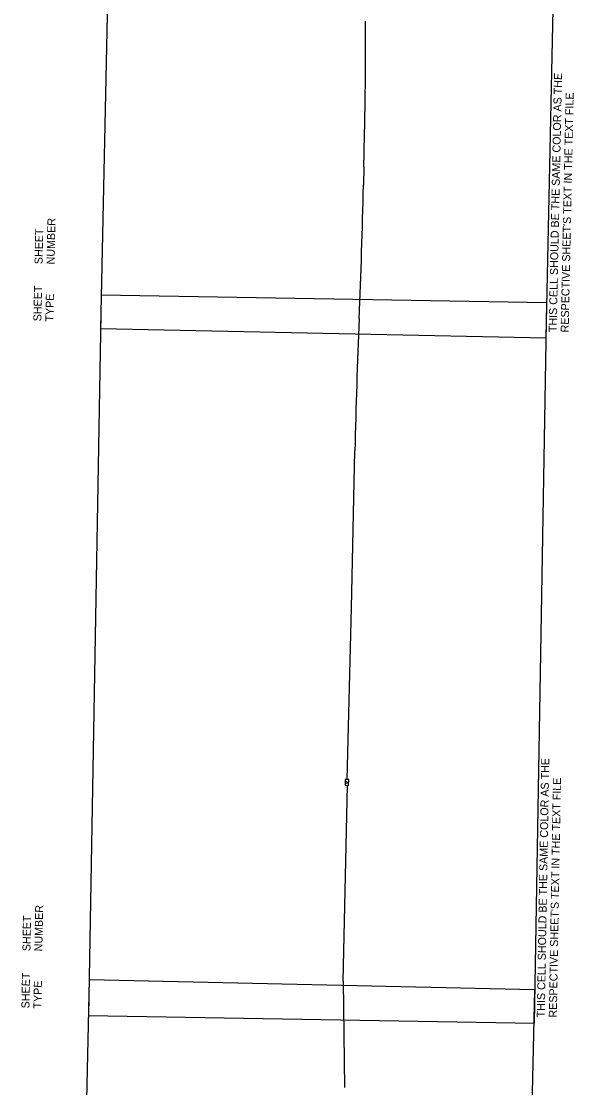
# Model space of a CAD drawing. Extents: x 601462 to 605493, y 331960 to 402715.
# Drawn here: x 603621 to 604829, y 342262 to 344593 of the extents above; entities that cross this region are included whole.
import ezdxf

# ---------------------------------------------------------------- set-up
doc = ezdxf.new("R2010")
doc.units = 0
for name, color, linetype in [('P_FTMS', 7, 'Continuous'), ('P_FTMSConduit', 7, 'Continuous'), ('P_MISC_TXT_2A (Construction)', 7, 'Continuous'), ('P_MISC_TXT_2B (Construction)', 7, 'Continuous')]:
    doc.layers.add(name, color=color, linetype=linetype)

# ---------------------------------------------------------------- blocks, each defined once
blk = doc.blocks.new('FTMS_FCV')
at = {"layer": 'P_FTMS'}
blk.add_line((13, 16), (1, -22), dxfattribs=at)
blk.add_lwpolyline([(39, 24), (-39, 24), (-39, -24), (39, -24)], close=True, dxfattribs=at)
blk.add_lwpolyline([(-12, 16), (1, -22)], dxfattribs=at)

msp = doc.modelspace()

# ---------------------------------------------------------------- linework, layer by layer
at = {"layer": 'P_FTMSConduit'}
for p, q in [((604369.9, 344275.3), (604369, 344235.3)), ((604342.8, 343310.7), (604350.3, 343653.9)), ((604333.3, 342935.7), (604342.8, 343310.7)), ((604325, 342494.7), (604334.3, 342922.8)), ((604325, 342495), (604327.2, 342262.1))]:
    msp.add_line(p, q, dxfattribs=at)
for centre, radius, start, end in [((590213.5, 344584.5), 14160.3, 359.37156, 0.03535), ((589440.8, 344649.6), 14933.7, 358.56399, 359.15428), ((590212.6, 344544.5), 14159.8, 357.56708, 358.74902), ((618387.2, 343347.4), 14040.2, 177.56708, 178.74902)]:
    msp.add_arc(centre, radius, start, end, dxfattribs=at)
at = {"layer": 'P_MISC_TXT_2A (Construction)'}
for points in [[(604768.7, 343901), (604801.9, 345475.6), (603827.1, 345496.2), (603793.9, 343921.5)], [(604708.5, 340900.9), (604744.2, 342475.5), (603769.4, 342497.6), (603733.8, 340923)]]:
    msp.add_lwpolyline(points, close=True, dxfattribs=at)
at = {"layer": 'P_MISC_TXT_2B (Construction)'}
msp.add_lwpolyline([(604742.8, 342403), (604770.2, 343977.8), (603795.4, 343994.8), (603767.9, 342420)], close=True, dxfattribs=at)

# ---------------------------------------------------------------- block references
at = {"layer": 'P_FTMS', "xscale": 0.1640416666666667, "yscale": 0.16404166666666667, "rotation": 87.23689791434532}
msp.add_blockref('FTMS_FCV', (604333, 342929.3), dxfattribs=at)

# ---------------------------------------------------------------- texts
at = {"layer": 'P_MISC_TXT_2A (Construction)'}
for s, p in [('THIS CELL SHOULD BE THE SAME COLOR AS THE', (604791.6, 343913.5)), ("RESPECTIVE SHEET'S TEXT IN THE TEXT FILE", (604817.8, 343912.9)), ('NUMBER', (603693.2, 344061.6)), ('SHEET', (603667, 344062.2)), ('SHEET', (603664.4, 343937.2)), ('TYPE', (603690.6, 343936.6))]:
    msp.add_text(s, height=17.5, rotation=88.794, dxfattribs=at).set_placement(p)
at = {"layer": 'P_MISC_TXT_2B (Construction)'}
for s, p in [('THIS CELL SHOULD BE THE SAME COLOR AS THE', (604765.6, 342415.6)), ("RESPECTIVE SHEET'S TEXT IN THE TEXT FILE", (604791.9, 342415.1)), ('NUMBER', (603666.7, 342559.8)), ('SHEET', (603640.5, 342560.2)), ('SHEET', (603638.3, 342435.2)), ('TYPE', (603664.6, 342434.8))]:
    msp.add_text(s, height=17.5, rotation=89.0014, dxfattribs=at).set_placement(p)

doc.saveas('drawing.dxf')
